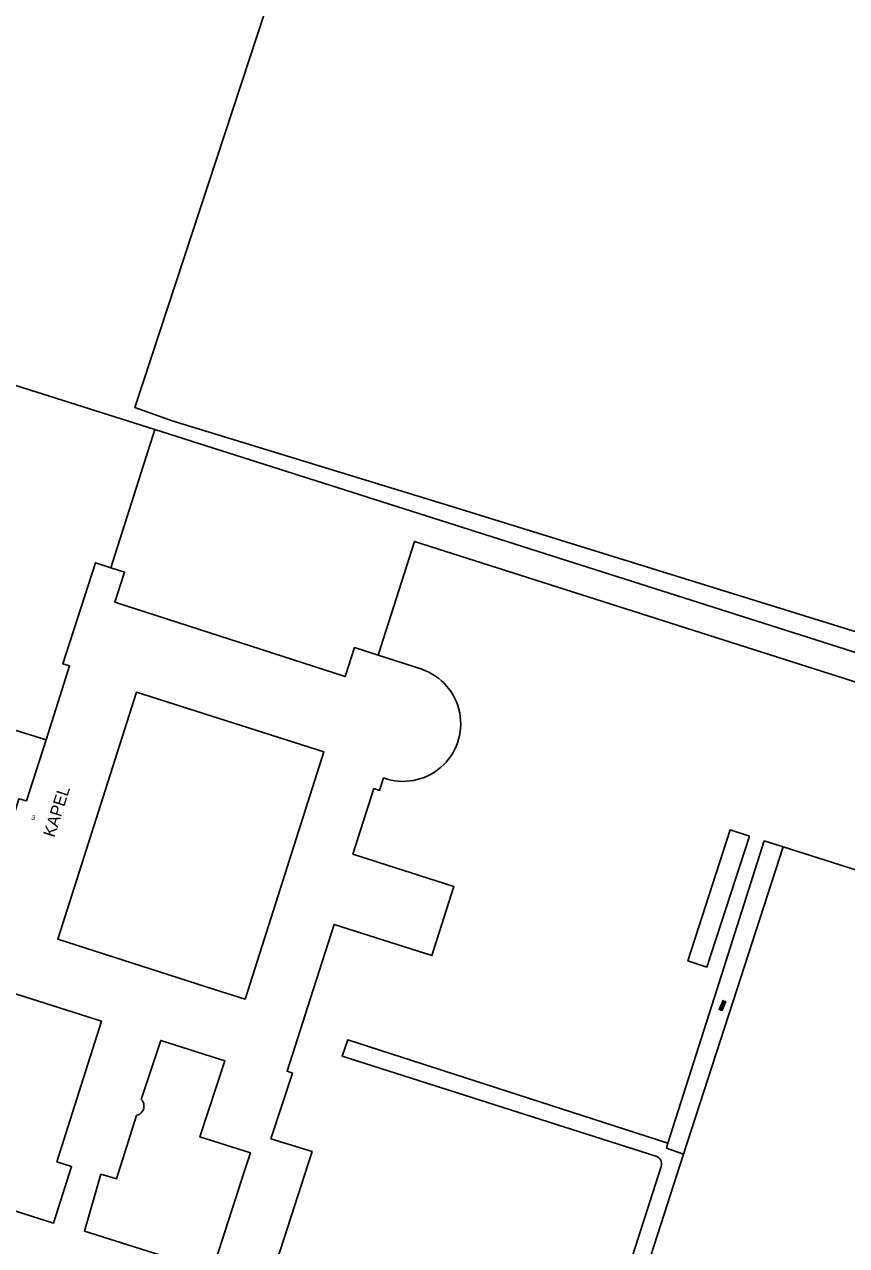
# Model space of a CAD drawing. Extents: x 135990 to 139000, y 393500 to 396000.
# Drawn here: x 137160.7 to 137331, y 394947 to 395199.8 of the extents above; entities that cross this region are included whole.
import ezdxf

# ---------------------------------------------------------------- set-up
doc = ezdxf.new("R2010")
doc.units = 0
for name, color, linetype in [('gg-afsc-muur', 7, 'Continuous'), ('gg-anno-huisnummerreeks BGT', 7, 'Continuous'), ('gg-bbg-bijgebouw', 7, 'Continuous'), ('gg-bbg-gedigitaliseerde bebouwing', 7, 'Continuous'), ('gg-bbg-gedigitaliseerde bijgebouw', 7, 'Continuous'), ('gg-bbg-hoofdgebouw', 7, 'Continuous'), ('gg-knt-onverhard', 7, 'Continuous'), ('gg-knt-verharding', 7, 'Continuous'), ('gt-anno-naam bijzondere bebouwing', 7, 'Continuous'), ('gt-grn-groengrens', 7, 'Continuous'), ('gt-grn-vlakafsluiter', 7, 'Continuous'), ('gt-symb-overige verharding', 7, 'Continuous'), ('gx-grn-maaiveld', 7, 'Continuous')]:
    doc.layers.add(name, color=color, linetype=linetype)

# ---------------------------------------------------------------- blocks, each defined once
blk = doc.blocks.new('gt0-OVH')
at = {"layer": 'gt-symb-overige verharding'}
for points in [[(-0.97, 0.3), (-0.97, 0.31), (-0.96, 0.32), (-0.97, 0.33), (-0.97, 0.34), (-0.98, 0.35), (-0.99, 0.35), (-1, 0.36), (-1.01, 0.35), (-1.02, 0.35), (-1.03, 0.34), (-1.03, 0.33), (-1.04, 0.32), (-1.03, 0.31), (-1.03, 0.3), (-1.02, 0.29), (-1.01, 0.29), (-1, 0.28), (-0.99, 0.29), (-0.98, 0.29)], [(-0.87, 0.11), (-0.87, 0.12), (-0.86, 0.13), (-0.87, 0.14), (-0.87, 0.15), (-0.88, 0.16), (-0.89, 0.16), (-0.9, 0.16), (-0.91, 0.16), (-0.92, 0.16), (-0.93, 0.15), (-0.93, 0.14), (-0.94, 0.13), (-0.93, 0.12), (-0.93, 0.11), (-0.92, 0.1), (-0.91, 0.09), (-0.9, 0.09), (-0.89, 0.09), (-0.88, 0.1)], [(-0.77, 0.3), (-0.77, 0.31), (-0.76, 0.32), (-0.77, 0.33), (-0.77, 0.34), (-0.78, 0.35), (-0.79, 0.35), (-0.8, 0.36), (-0.81, 0.35), (-0.82, 0.35), (-0.83, 0.34), (-0.83, 0.33), (-0.84, 0.32), (-0.83, 0.31), (-0.83, 0.3), (-0.82, 0.29), (-0.81, 0.29), (-0.8, 0.28), (-0.79, 0.29), (-0.78, 0.29)], [(-0.67, 0.11), (-0.67, 0.12), (-0.66, 0.13), (-0.67, 0.14), (-0.67, 0.15), (-0.68, 0.16), (-0.69, 0.16), (-0.7, 0.16), (-0.71, 0.16), (-0.72, 0.16), (-0.73, 0.15), (-0.73, 0.14), (-0.74, 0.13), (-0.73, 0.12), (-0.73, 0.11), (-0.72, 0.1), (-0.71, 0.09), (-0.7, 0.09), (-0.69, 0.09), (-0.68, 0.1)], [(-0.57, 0.3), (-0.57, 0.31), (-0.56, 0.32), (-0.57, 0.33), (-0.57, 0.34), (-0.58, 0.35), (-0.59, 0.35), (-0.6, 0.36), (-0.61, 0.35), (-0.62, 0.35), (-0.63, 0.34), (-0.63, 0.33), (-0.64, 0.32), (-0.63, 0.31), (-0.63, 0.3), (-0.62, 0.29), (-0.61, 0.29), (-0.6, 0.28), (-0.59, 0.29), (-0.58, 0.29)], [(-0.47, 0.11), (-0.47, 0.12), (-0.46, 0.13), (-0.47, 0.14), (-0.47, 0.15), (-0.48, 0.16), (-0.49, 0.16), (-0.5, 0.16), (-0.51, 0.16), (-0.52, 0.16), (-0.53, 0.15), (-0.53, 0.14), (-0.54, 0.13), (-0.53, 0.12), (-0.53, 0.11), (-0.52, 0.1), (-0.51, 0.09), (-0.5, 0.09), (-0.49, 0.09), (-0.48, 0.1)], [(-0.37, 0.3), (-0.37, 0.31), (-0.36, 0.32), (-0.37, 0.33), (-0.37, 0.34), (-0.38, 0.35), (-0.39, 0.35), (-0.4, 0.36), (-0.41, 0.35), (-0.42, 0.35), (-0.43, 0.34), (-0.43, 0.33), (-0.44, 0.32), (-0.43, 0.31), (-0.43, 0.3), (-0.42, 0.29), (-0.41, 0.29), (-0.4, 0.28), (-0.39, 0.29), (-0.38, 0.29)], [(-0.27, 0.11), (-0.27, 0.12), (-0.26, 0.13), (-0.27, 0.14), (-0.27, 0.15), (-0.28, 0.16), (-0.29, 0.16), (-0.3, 0.16), (-0.31, 0.16), (-0.32, 0.16), (-0.33, 0.15), (-0.33, 0.14), (-0.34, 0.13), (-0.33, 0.12), (-0.33, 0.11), (-0.32, 0.1), (-0.31, 0.09), (-0.3, 0.09), (-0.29, 0.09), (-0.28, 0.1)], [(-0.17, 0.3), (-0.17, 0.31), (-0.16, 0.32), (-0.17, 0.33), (-0.17, 0.34), (-0.18, 0.35), (-0.19, 0.35), (-0.2, 0.36), (-0.21, 0.35), (-0.22, 0.35), (-0.23, 0.34), (-0.23, 0.33), (-0.24, 0.32), (-0.23, 0.31), (-0.23, 0.3), (-0.22, 0.29), (-0.21, 0.29), (-0.2, 0.28), (-0.19, 0.29), (-0.18, 0.29)], [(-0.07, 0.11), (-0.07, 0.12), (-0.06, 0.13), (-0.07, 0.14), (-0.07, 0.15), (-0.08, 0.16), (-0.09, 0.16), (-0.1, 0.16), (-0.11, 0.16), (-0.12, 0.16), (-0.13, 0.15), (-0.13, 0.14), (-0.14, 0.13), (-0.13, 0.12), (-0.13, 0.11), (-0.12, 0.1), (-0.11, 0.09), (-0.1, 0.09), (-0.09, 0.09), (-0.08, 0.1)], [(0.03, 0.3), (0.03, 0.31), (0.04, 0.32), (0.03, 0.33), (0.03, 0.34), (0.02, 0.35), (0.01, 0.35), (0, 0.36), (-0.01, 0.35), (-0.02, 0.35), (-0.03, 0.34), (-0.03, 0.33), (-0.04, 0.32), (-0.03, 0.31), (-0.03, 0.3), (-0.02, 0.29), (-0.01, 0.29), (0, 0.28), (0.01, 0.29), (0.02, 0.29)], [(0.13, 0.11), (0.13, 0.12), (0.14, 0.13), (0.13, 0.14), (0.13, 0.15), (0.12, 0.16), (0.11, 0.16), (0.1, 0.16), (0.09, 0.16), (0.08, 0.16), (0.07, 0.15), (0.07, 0.14), (0.06, 0.13), (0.07, 0.12), (0.07, 0.11), (0.08, 0.1), (0.09, 0.09), (0.1, 0.09), (0.11, 0.09), (0.12, 0.1)], [(0.23, 0.3), (0.23, 0.31), (0.24, 0.32), (0.23, 0.33), (0.23, 0.34), (0.22, 0.35), (0.21, 0.35), (0.2, 0.36), (0.19, 0.35), (0.18, 0.35), (0.17, 0.34), (0.17, 0.33), (0.16, 0.32), (0.17, 0.31), (0.17, 0.3), (0.18, 0.29), (0.19, 0.29), (0.2, 0.28), (0.21, 0.29), (0.22, 0.29)], [(0.33, 0.11), (0.33, 0.12), (0.34, 0.13), (0.33, 0.14), (0.33, 0.15), (0.32, 0.16), (0.31, 0.16), (0.3, 0.16), (0.29, 0.16), (0.28, 0.16), (0.27, 0.15), (0.27, 0.14), (0.26, 0.13), (0.27, 0.12), (0.27, 0.11), (0.28, 0.1), (0.29, 0.09), (0.3, 0.09), (0.31, 0.09), (0.32, 0.1)], [(0.43, 0.3), (0.43, 0.31), (0.44, 0.32), (0.43, 0.33), (0.43, 0.34), (0.42, 0.35), (0.41, 0.35), (0.4, 0.36), (0.39, 0.35), (0.38, 0.35), (0.37, 0.34), (0.37, 0.33), (0.36, 0.32), (0.37, 0.31), (0.37, 0.3), (0.38, 0.29), (0.39, 0.29), (0.4, 0.28), (0.41, 0.29), (0.42, 0.29)], [(0.53, 0.11), (0.53, 0.12), (0.54, 0.13), (0.53, 0.14), (0.53, 0.15), (0.52, 0.16), (0.51, 0.16), (0.5, 0.16), (0.49, 0.16), (0.48, 0.16), (0.47, 0.15), (0.47, 0.14), (0.46, 0.13), (0.47, 0.12), (0.47, 0.11), (0.48, 0.1), (0.49, 0.09), (0.5, 0.09), (0.51, 0.09), (0.52, 0.1)], [(0.63, 0.3), (0.63, 0.31), (0.64, 0.32), (0.63, 0.33), (0.63, 0.34), (0.62, 0.35), (0.61, 0.35), (0.6, 0.36), (0.59, 0.35), (0.58, 0.35), (0.57, 0.34), (0.57, 0.33), (0.56, 0.32), (0.57, 0.31), (0.57, 0.3), (0.58, 0.29), (0.59, 0.29), (0.6, 0.28), (0.61, 0.29), (0.62, 0.29)], [(0.73, 0.11), (0.73, 0.12), (0.74, 0.13), (0.73, 0.14), (0.73, 0.15), (0.72, 0.16), (0.71, 0.16), (0.7, 0.16), (0.69, 0.16), (0.68, 0.16), (0.67, 0.15), (0.67, 0.14), (0.66, 0.13), (0.67, 0.12), (0.67, 0.11), (0.68, 0.1), (0.69, 0.09), (0.7, 0.09), (0.71, 0.09), (0.72, 0.1)], [(0.83, 0.3), (0.83, 0.31), (0.84, 0.32), (0.83, 0.33), (0.83, 0.34), (0.82, 0.35), (0.81, 0.35), (0.8, 0.36), (0.79, 0.35), (0.78, 0.35), (0.77, 0.34), (0.77, 0.33), (0.76, 0.32), (0.77, 0.31), (0.77, 0.3), (0.78, 0.29), (0.79, 0.29), (0.8, 0.28), (0.81, 0.29), (0.82, 0.29)], [(0.93, 0.11), (0.93, 0.12), (0.94, 0.13), (0.93, 0.14), (0.93, 0.15), (0.92, 0.16), (0.91, 0.16), (0.9, 0.16), (0.89, 0.16), (0.88, 0.16), (0.87, 0.15), (0.87, 0.14), (0.86, 0.13), (0.87, 0.12), (0.87, 0.11), (0.88, 0.1), (0.89, 0.09), (0.9, 0.09), (0.91, 0.09), (0.92, 0.1)], [(1.03, 0.3), (1.03, 0.31), (1.04, 0.32), (1.03, 0.33), (1.03, 0.34), (1.02, 0.35), (1.01, 0.35), (1, 0.36), (0.99, 0.35), (0.98, 0.35), (0.97, 0.34), (0.97, 0.33), (0.96, 0.32), (0.97, 0.31), (0.97, 0.3), (0.98, 0.29), (0.99, 0.29), (1, 0.28), (1.01, 0.29), (1.02, 0.29)], [(-0.97, -0.14), (-0.97, -0.13), (-0.96, -0.12), (-0.97, -0.11), (-0.97, -0.1), (-0.98, -0.09), (-0.99, -0.09), (-1, -0.08), (-1.01, -0.09), (-1.02, -0.09), (-1.03, -0.1), (-1.03, -0.11), (-1.04, -0.12), (-1.03, -0.13), (-1.03, -0.14), (-1.02, -0.15), (-1.01, -0.15), (-1, -0.16), (-0.99, -0.15), (-0.98, -0.15)], [(-0.87, -0.33), (-0.87, -0.32), (-0.86, -0.31), (-0.87, -0.3), (-0.87, -0.29), (-0.88, -0.28), (-0.89, -0.28), (-0.9, -0.28), (-0.91, -0.28), (-0.92, -0.28), (-0.93, -0.29), (-0.93, -0.3), (-0.94, -0.31), (-0.93, -0.32), (-0.93, -0.33), (-0.92, -0.34), (-0.91, -0.35), (-0.9, -0.35), (-0.89, -0.35), (-0.88, -0.34)], [(-0.77, -0.14), (-0.77, -0.13), (-0.76, -0.12), (-0.77, -0.11), (-0.77, -0.1), (-0.78, -0.09), (-0.79, -0.09), (-0.8, -0.08), (-0.81, -0.09), (-0.82, -0.09), (-0.83, -0.1), (-0.83, -0.11), (-0.84, -0.12), (-0.83, -0.13), (-0.83, -0.14), (-0.82, -0.15), (-0.81, -0.15), (-0.8, -0.16), (-0.79, -0.15), (-0.78, -0.15)], [(-0.67, -0.33), (-0.67, -0.32), (-0.66, -0.31), (-0.67, -0.3), (-0.67, -0.29), (-0.68, -0.28), (-0.69, -0.28), (-0.7, -0.28), (-0.71, -0.28), (-0.72, -0.28), (-0.73, -0.29), (-0.73, -0.3), (-0.74, -0.31), (-0.73, -0.32), (-0.73, -0.33), (-0.72, -0.34), (-0.71, -0.35), (-0.7, -0.35), (-0.69, -0.35), (-0.68, -0.34)], [(-0.57, -0.14), (-0.57, -0.13), (-0.56, -0.12), (-0.57, -0.11), (-0.57, -0.1), (-0.58, -0.09), (-0.59, -0.09), (-0.6, -0.08), (-0.61, -0.09), (-0.62, -0.09), (-0.63, -0.1), (-0.63, -0.11), (-0.64, -0.12), (-0.63, -0.13), (-0.63, -0.14), (-0.62, -0.15), (-0.61, -0.15), (-0.6, -0.16), (-0.59, -0.15), (-0.58, -0.15)], [(-0.47, -0.33), (-0.47, -0.32), (-0.46, -0.31), (-0.47, -0.3), (-0.47, -0.29), (-0.48, -0.28), (-0.49, -0.28), (-0.5, -0.28), (-0.51, -0.28), (-0.52, -0.28), (-0.53, -0.29), (-0.53, -0.3), (-0.54, -0.31), (-0.53, -0.32), (-0.53, -0.33), (-0.52, -0.34), (-0.51, -0.35), (-0.5, -0.35), (-0.49, -0.35), (-0.48, -0.34)], [(-0.37, -0.14), (-0.37, -0.13), (-0.36, -0.12), (-0.37, -0.11), (-0.37, -0.1), (-0.38, -0.09), (-0.39, -0.09), (-0.4, -0.08), (-0.41, -0.09), (-0.42, -0.09), (-0.43, -0.1), (-0.43, -0.11), (-0.44, -0.12), (-0.43, -0.13), (-0.43, -0.14), (-0.42, -0.15), (-0.41, -0.15), (-0.4, -0.16), (-0.39, -0.15), (-0.38, -0.15)], [(-0.27, -0.33), (-0.27, -0.32), (-0.26, -0.31), (-0.27, -0.3), (-0.27, -0.29), (-0.28, -0.28), (-0.29, -0.28), (-0.3, -0.28), (-0.31, -0.28), (-0.32, -0.28), (-0.33, -0.29), (-0.33, -0.3), (-0.34, -0.31), (-0.33, -0.32), (-0.33, -0.33), (-0.32, -0.34), (-0.31, -0.35), (-0.3, -0.35), (-0.29, -0.35), (-0.28, -0.34)], [(-0.17, -0.14), (-0.17, -0.13), (-0.16, -0.12), (-0.17, -0.11), (-0.17, -0.1), (-0.18, -0.09), (-0.19, -0.09), (-0.2, -0.08), (-0.21, -0.09), (-0.22, -0.09), (-0.23, -0.1), (-0.23, -0.11), (-0.24, -0.12), (-0.23, -0.13), (-0.23, -0.14), (-0.22, -0.15), (-0.21, -0.15), (-0.2, -0.16), (-0.19, -0.15), (-0.18, -0.15)], [(-0.07, -0.33), (-0.07, -0.32), (-0.06, -0.31), (-0.07, -0.3), (-0.07, -0.29), (-0.08, -0.28), (-0.09, -0.28), (-0.1, -0.28), (-0.11, -0.28), (-0.12, -0.28), (-0.13, -0.29), (-0.13, -0.3), (-0.14, -0.31), (-0.13, -0.32), (-0.13, -0.33), (-0.12, -0.34), (-0.11, -0.35), (-0.1, -0.35), (-0.09, -0.35), (-0.08, -0.34)], [(0.03, -0.14), (0.03, -0.13), (0.04, -0.12), (0.03, -0.11), (0.03, -0.1), (0.02, -0.09), (0.01, -0.09), (0, -0.08), (-0.01, -0.09), (-0.02, -0.09), (-0.03, -0.1), (-0.03, -0.11), (-0.04, -0.12), (-0.03, -0.13), (-0.03, -0.14), (-0.02, -0.15), (-0.01, -0.15), (0, -0.16), (0.01, -0.15), (0.02, -0.15)], [(0.13, -0.33), (0.13, -0.32), (0.14, -0.31), (0.13, -0.3), (0.13, -0.29), (0.12, -0.28), (0.11, -0.28), (0.1, -0.28), (0.09, -0.28), (0.08, -0.28), (0.07, -0.29), (0.07, -0.3), (0.06, -0.31), (0.07, -0.32), (0.07, -0.33), (0.08, -0.34), (0.09, -0.35), (0.1, -0.35), (0.11, -0.35), (0.12, -0.34)], [(0.23, -0.14), (0.23, -0.13), (0.24, -0.12), (0.23, -0.11), (0.23, -0.1), (0.22, -0.09), (0.21, -0.09), (0.2, -0.08), (0.19, -0.09), (0.18, -0.09), (0.17, -0.1), (0.17, -0.11), (0.16, -0.12), (0.17, -0.13), (0.17, -0.14), (0.18, -0.15), (0.19, -0.15), (0.2, -0.16), (0.21, -0.15), (0.22, -0.15)], [(0.33, -0.33), (0.33, -0.32), (0.34, -0.31), (0.33, -0.3), (0.33, -0.29), (0.32, -0.28), (0.31, -0.28), (0.3, -0.28), (0.29, -0.28), (0.28, -0.28), (0.27, -0.29), (0.27, -0.3), (0.26, -0.31), (0.27, -0.32), (0.27, -0.33), (0.28, -0.34), (0.29, -0.35), (0.3, -0.35), (0.31, -0.35), (0.32, -0.34)], [(0.43, -0.14), (0.43, -0.13), (0.44, -0.12), (0.43, -0.11), (0.43, -0.1), (0.42, -0.09), (0.41, -0.09), (0.4, -0.08), (0.39, -0.09), (0.38, -0.09), (0.37, -0.1), (0.37, -0.11), (0.36, -0.12), (0.37, -0.13), (0.37, -0.14), (0.38, -0.15), (0.39, -0.15), (0.4, -0.16), (0.41, -0.15), (0.42, -0.15)], [(0.53, -0.33), (0.53, -0.32), (0.54, -0.31), (0.53, -0.3), (0.53, -0.29), (0.52, -0.28), (0.51, -0.28), (0.5, -0.28), (0.49, -0.28), (0.48, -0.28), (0.47, -0.29), (0.47, -0.3), (0.46, -0.31), (0.47, -0.32), (0.47, -0.33), (0.48, -0.34), (0.49, -0.35), (0.5, -0.35), (0.51, -0.35), (0.52, -0.34)], [(0.63, -0.14), (0.63, -0.13), (0.64, -0.12), (0.63, -0.11), (0.63, -0.1), (0.62, -0.09), (0.61, -0.09), (0.6, -0.08), (0.59, -0.09), (0.58, -0.09), (0.57, -0.1), (0.57, -0.11), (0.56, -0.12), (0.57, -0.13), (0.57, -0.14), (0.58, -0.15), (0.59, -0.15), (0.6, -0.16), (0.61, -0.15), (0.62, -0.15)], [(0.73, -0.33), (0.73, -0.32), (0.74, -0.31), (0.73, -0.3), (0.73, -0.29), (0.72, -0.28), (0.71, -0.28), (0.7, -0.28), (0.69, -0.28), (0.68, -0.28), (0.67, -0.29), (0.67, -0.3), (0.66, -0.31), (0.67, -0.32), (0.67, -0.33), (0.68, -0.34), (0.69, -0.35), (0.7, -0.35), (0.71, -0.35), (0.72, -0.34)], [(0.83, -0.14), (0.83, -0.13), (0.84, -0.12), (0.83, -0.11), (0.83, -0.1), (0.82, -0.09), (0.81, -0.09), (0.8, -0.08), (0.79, -0.09), (0.78, -0.09), (0.77, -0.1), (0.77, -0.11), (0.76, -0.12), (0.77, -0.13), (0.77, -0.14), (0.78, -0.15), (0.79, -0.15), (0.8, -0.16), (0.81, -0.15), (0.82, -0.15)], [(0.93, -0.33), (0.93, -0.32), (0.94, -0.31), (0.93, -0.3), (0.93, -0.29), (0.92, -0.28), (0.91, -0.28), (0.9, -0.28), (0.89, -0.28), (0.88, -0.28), (0.87, -0.29), (0.87, -0.3), (0.86, -0.31), (0.87, -0.32), (0.87, -0.33), (0.88, -0.34), (0.89, -0.35), (0.9, -0.35), (0.91, -0.35), (0.92, -0.34)], [(1.03, -0.14), (1.03, -0.13), (1.04, -0.12), (1.03, -0.11), (1.03, -0.1), (1.02, -0.09), (1.01, -0.09), (1, -0.08), (0.99, -0.09), (0.98, -0.09), (0.97, -0.1), (0.97, -0.11), (0.96, -0.12), (0.97, -0.13), (0.97, -0.14), (0.98, -0.15), (0.99, -0.15), (1, -0.16), (1.01, -0.15), (1.02, -0.15)]]:
    blk.add_lwpolyline(points, close=True, dxfattribs=at)

msp = doc.modelspace()

# ---------------------------------------------------------------- linework, layer by layer
at = {"layer": 'gg-afsc-muur'}
for p, q in [((137117.126, 395138.354), (137187.73, 395115.93)), ((137117.126, 395138.354), (137187.73, 395115.93)), ((137178.648, 395087.353), (137187.73, 395115.93)), ((137187.73, 395115.93), (137462.233, 395028.732)), ((137187.73, 395115.93), (137462.233, 395028.732))]:
    msp.add_line(p, q, dxfattribs=at)
at = {"layer": 'gg-bbg-bijgebouw'}
msp.add_line((137302.13, 395004.692), (137310.91, 395031.782), dxfattribs=at)
at = {"layer": 'gg-bbg-gedigitaliseerde bebouwing'}
msp.add_line((137234.015, 395069.232), (137243.054, 395066.318), dxfattribs=at)
for points in [[(137178.648, 395087.353), (137181.509, 395086.433), (137179.496, 395080.189), (137227.199, 395064.812), (137229.131, 395070.806), (137234.015, 395069.232)], [(137207.078, 395000), (137222.781, 395049.233), (137183.971, 395061.611), (137167.646, 395010.429), (137200.343, 395000)], [(137235.157, 395043.838), (137234.332, 395041.258), (137233.147, 395041.637), (137228.805, 395028.065), (137249.702, 395021.379), (137245.13, 395007.051)], [(137200.343, 395000), (137206.457, 394998.05), (137207.078, 395000)]]:
    msp.add_lwpolyline(points, dxfattribs=at)
msp.add_arc((137239.206, 395055.043), 11.914, 250.12931, 71.15895, dxfattribs=at)
at = {"layer": 'gg-bbg-gedigitaliseerde bijgebouw'}
msp.add_lwpolyline([(137302.13, 395004.692), (137298.165, 395005.984), (137306.943, 395033.067), (137310.91, 395031.782)], dxfattribs=at)
at = {"layer": 'gg-bbg-hoofdgebouw'}
msp.add_line((137206.403, 394962.697), (137200.304, 394943.862), dxfattribs=at)
for points in [[(137165.225, 395051.755), (137170.11, 395067.07), (137168.73, 395067.432), (137175.48, 395088.372), (137178.648, 395087.353)], [(137157.956, 395033.981), (137159.58, 395039.492), (137161.18, 395039.072), (137165.225, 395051.755)], [(137245.13, 395007.051), (137224.88, 395013.53), (137220.549, 395000)], [(137156.261, 395000), (137176.74, 394993.46), (137167.47, 394964.4), (137170.52, 394963.428), (137166.76, 394951.648), (137135.04, 394961.768), (137130.583, 394948.941)], [(137189.622, 394871.532), (137220.35, 394966.49), (137211.811, 394969.148), (137216.29, 394982.72), (137215.16, 394983.169), (137220.549, 395000)], [(137206.403, 394962.697), (137207.55, 394966.238), (137197.11, 394969.52), (137202.29, 394985.289), (137189, 394989.52), (137184.95, 394977.269)], [(137188.741, 394945.143), (137173.17, 394950.001), (137176.55, 394961.81), (137179.79, 394960.828), (137183.98, 394973.99)]]:
    msp.add_lwpolyline(points, dxfattribs=at)
for centre, radius, start, end in [((137183.564, 394975.893), 1.953, 324.99943, 44.80135), ((137183.571, 394975.896), 1.949, 282.12194, 324.83279)]:
    msp.add_arc(centre, radius, start, end, dxfattribs=at)
at = {"layer": 'gg-knt-onverhard'}
for p, q in [((137304.155, 395000), (137313.97, 395030.842)), ((137308.311, 395000), (137317.89, 395029.561)), ((137294.04, 394968.218), (137304.155, 395000)), ((137297.28, 394965.96), (137308.311, 395000))]:
    msp.add_line(p, q, dxfattribs=at)
at = {"layer": 'gg-knt-verharding'}
msp.add_line((137275.232, 394909.345), (137292.652, 394963.384), dxfattribs=at)
for points in [[(137291.55, 394965.53), (137226.551, 394986.229), (137227.71, 394989.629), (137294.04, 394968.218)], [(137297.28, 394965.96), (137277.09, 394903.44), (137411.04, 394861.251), (137412.565, 394860.822)], [(137294.04, 394968.218), (137293.72, 394967.19), (137297.28, 394965.96)]]:
    msp.add_lwpolyline(points, dxfattribs=at)
msp.add_arc((137291.029, 394963.907), 1.705, 342.1501, 72.21212, dxfattribs=at)
at = {"layer": 'gt-grn-groengrens'}
msp.add_line((137449.06, 394987.836), (137317.89, 395029.561), dxfattribs=at)
msp.add_lwpolyline([(137460.422, 395023.11), (137241.514, 395092.79), (137234.015, 395069.232)], dxfattribs=at)
at = {"layer": 'gt-grn-vlakafsluiter'}
for p, q in [((137157.71, 395054.05), (137165.225, 395051.755)), ((137313.97, 395030.842), (137317.89, 395029.561))]:
    msp.add_line(p, q, dxfattribs=at)
at = {"layer": 'gx-grn-maaiveld'}
msp.add_lwpolyline([(137501.247, 395020.345), (137431.566, 395042.841), (137345.047, 395070.357), (137250.194, 395099.726), (137191.324, 395117.718), (137183.631, 395120.527), (137210.691, 395202.765), (137329.382, 395206.205), (137519.555, 395214.104), (137603.31, 395217.962)], dxfattribs=at)

# ---------------------------------------------------------------- block references
at = {"layer": 'gt-symb-overige verharding', "rotation": 66.2819901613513}
msp.add_blockref('gt0-OVH', (137305.346, 394996.708), dxfattribs=at)

# ---------------------------------------------------------------- texts
at = {"layer": 'gg-anno-huisnummerreeks BGT'}
msp.add_text('3', height=1, rotation=343.6, dxfattribs=at).set_placement((137162.091, 395035.236))
at = {"layer": 'gt-anno-naam bijzondere bebouwing'}
msp.add_text('KAPEL', height=2.5, rotation=72.3077, dxfattribs=at).set_placement((137166.948, 395031.373))

doc.saveas('drawing.dxf')
